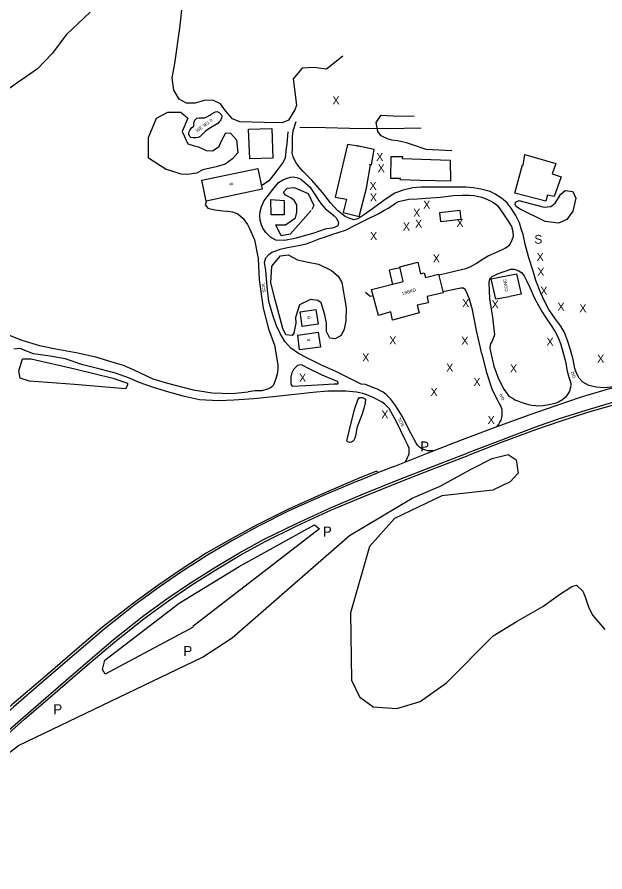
# Model space of a CAD drawing. Extents: x 2030130 to 2036320, y 723205 to 762423.
# Drawn here: x 2034000 to 2034735, y 739838 to 740906 of the extents above; entities that cross this region are included whole.
import ezdxf

# ---------------------------------------------------------------- set-up
doc = ezdxf.new("R2010")
doc.units = 0
for name, color, linetype in [('Draft_Station Labels Major', 7, 'Continuous'), ('Draft_Station Tics Major', 7, 'Continuous'), ('Draft_Station Tics Minor', 7, 'Continuous'), ('Exist Terrain Model Ground Surface', 7, 'Continuous'), ('Old_Level_23', 7, 'Continuous'), ('Old_Level_28', 7, 'Continuous'), ('Prop Alignment Horizontal', 7, 'Continuous'), ('Prop Alignment Vertical', 7, 'Continuous'), ('Prop Horizontal Alignment Ramp', 7, 'Continuous')]:
    doc.layers.add(name, color=color, linetype=linetype)

msp = doc.modelspace()

# ---------------------------------------------------------------- linework, layer by layer
at = {"layer": 'Draft_Station Labels Major'}
for p, q in [((2034469.7, 740344.2), (2034513.5, 740361.4)), ((2034518.8, 740344.3), (2034562.3, 740361.2)), ((2034520, 740341.6), (2034563.5, 740358.3)), ((2034425.9, 740326.7), (2034450.1, 740336.4)), ((2034449.1, 740338.7), (2034451.3, 740336.8))]:
    msp.add_line(p, q, dxfattribs=at)
for points in [[(2034591.3, 740688), (2034579.5, 740691), (2034570.1, 740692.6), (2034561, 740693.4), (2034549.3, 740693.5), (2034536.5, 740693.4), (2034517.6, 740693.4), (2034504.3, 740693.5), (2034494.4, 740692.8), (2034482.3, 740689.8), (2034472, 740686.1), (2034459.9, 740678), (2034443.8, 740666.6), (2034432.8, 740658.5), (2034427.7, 740655.2), (2034423.8, 740653.4), (2034420.5, 740652.9), (2034417.3, 740653.8), (2034413.5, 740655.1), (2034409.6, 740657), (2034400, 740664.6), (2034391.5, 740674.1), (2034381.4, 740686.8), (2034367.9, 740702.4), (2034356.9, 740713.5), (2034351.4, 740719.9), (2034348.6, 740723.9), (2034346, 740728.5), (2034344.7, 740731.5), (2034343.7, 740736.3), (2034343.9, 740740.4), (2034344, 740744.1), (2034344, 740748.5), (2034344.1, 740756.8), (2034344.9, 740763.9), (2034348.4, 740775.8)], [(2034338.2, 740762.7), (2034336.8, 740747.7), (2034335.9, 740742.5), (2034334.6, 740730.3), (2034332.1, 740724.9), (2034325.8, 740716.3), (2034319.5, 740707.7), (2034314.2, 740701.3), (2034305, 740695.3)], [(2034384.8, 740640.9), (2034370.8, 740636.1), (2034357.2, 740632.4), (2034347, 740629.6), (2034333.9, 740626.7), (2034323.2, 740627.5), (2034316.5, 740631.1), (2034310.6, 740637), (2034307, 740642.3), (2034305, 740646.6), (2034303.6, 740652.4), (2034303.1, 740658.1), (2034303.6, 740663.2), (2034305.1, 740668.9), (2034308.1, 740676.1), (2034319.2, 740690.8), (2034326.4, 740699.3), (2034331.8, 740702.9), (2034337.1, 740704.9), (2034341.6, 740706.2), (2034345.3, 740706.5), (2034350.5, 740705.4), (2034354.5, 740703.4), (2034356.6, 740702.1), (2034366, 740693.6), (2034369.5, 740688.2), (2034372.9, 740682.7), (2034376.5, 740677.2), (2034379.2, 740673.2), (2034384.9, 740666.8), (2034389.5, 740663), (2034392.7, 740660.5), (2034396.1, 740657.7), (2034399, 740654.7), (2034401.6, 740649.5), (2034400.5, 740645.3), (2034397.1, 740643.4), (2034393.5, 740642.5), (2034387, 740641.5), (2034384.9, 740641.1)], [(2034749.2, 740444.3), (2034734.1, 740442.7), (2034723.5, 740443.5), (2034714.6, 740445.5), (2034707.1, 740449.8), (2034702.5, 740454.7), (2034699.3, 740460.1), (2034697, 740466.8), (2034694.9, 740478.1), (2034691.7, 740490.3), (2034687.9, 740501.9), (2034684, 740511.9), (2034679.4, 740519.7), (2034672.1, 740530), (2034664.4, 740540.5), (2034659.3, 740550.2), (2034654.3, 740561.2), (2034648.3, 740576.7), (2034644.8, 740588.4), (2034639.5, 740605.4), (2034635, 740622.4), (2034632.3, 740634.2), (2034630, 740641.4), (2034627.6, 740648.8), (2034623.1, 740658.1), (2034617.4, 740667.4), (2034612.3, 740673.8), (2034605.2, 740679.9), (2034597.2, 740684.9), (2034591.3, 740688)], [(2034236.4, 740676.3), (2034234.8, 740671.5), (2034238, 740667.4), (2034246.6, 740665.4), (2034256.7, 740664), (2034262.8, 740663.7), (2034268.8, 740662.8), (2034275.7, 740660.1), (2034282.4, 740654.5), (2034287.8, 740646.9), (2034290, 740642), (2034296.6, 740627.6), (2034301, 740604.6), (2034302.4, 740577.7), (2034307.1, 740542.3), (2034314.1, 740516.6), (2034321.3, 740496.1), (2034325.6, 740471.3), (2034325.7, 740466), (2034324.6, 740459.9), (2034323.1, 740454.3), (2034321.6, 740449.5), (2034319.6, 740445.6), (2034318, 740443.8), (2034316.3, 740442.6), (2034314, 740441.5), (2034309.7, 740440.2), (2034305, 740439.2), (2034301, 740439.1), (2034297.2, 740438.9), (2034288.3, 740437.6)], [(2034422.4, 740451.1), (2034398, 740463), (2034379.2, 740471.7), (2034361.9, 740480.2), (2034351.6, 740485.5), (2034341.8, 740492.4), (2034334.2, 740500.5), (2034328.5, 740510.7), (2034324.1, 740520.4), (2034319.2, 740533.4), (2034314.4, 740550.7), (2034312.2, 740569), (2034310.6, 740589.4), (2034309.1, 740599.5), (2034310.7, 740605.3), (2034314.3, 740609.5), (2034318.1, 740612.2), (2034324.4, 740614.4), (2034328.6, 740615.9), (2034337.5, 740618), (2034351.3, 740620.5), (2034361.2, 740622.8), (2034367, 740624.8), (2034372.9, 740627.3), (2034377.4, 740629), (2034385.3, 740631.6), (2034393, 740634.2), (2034402.3, 740637.5), (2034410.2, 740640), (2034424, 740646.8), (2034435.6, 740652.6), (2034451.9, 740660.6), (2034458.3, 740664.3), (2034464.3, 740667.8), (2034469.6, 740671.5), (2034472.7, 740673.6), (2034476.5, 740675.6), (2034489.3, 740678.7), (2034500, 740679.1), (2034517, 740680.2), (2034528.9, 740681.1), (2034545.4, 740683), (2034556, 740683.4), (2034565.1, 740683.5), (2034571.1, 740683.1), (2034575, 740682.5), (2034580.6, 740681), (2034587.7, 740678.3), (2034593.9, 740675.2), (2034600.4, 740670.6)], [(2034600.4, 740670.6), (2034607.9, 740660), (2034613.7, 740650.9), (2034617.6, 740644.4), (2034619.4, 740638.3), (2034620, 740631.7), (2034618.3, 740627.2), (2034616.2, 740622.8), (2034613.6, 740619.9)], [(2034526.8, 740583.9), (2034534.4, 740585.6), (2034549.8, 740589.2), (2034560.8, 740591.7), (2034566.2, 740593.8), (2034573.5, 740598.1), (2034580.3, 740602.6), (2034588.6, 740607.7), (2034595.2, 740610.8), (2034601.9, 740613.4), (2034607.2, 740615.9), (2034610.3, 740617.7), (2034613.6, 740619.9)], [(2034617.7, 740590.9), (2034600, 740585), (2034593.1, 740581.6), (2034590.4, 740578.5), (2034589.5, 740574.2), (2034590.4, 740554.1), (2034594.2, 740531.2), (2034596.5, 740509.1), (2034593.6, 740501.1), (2034592, 740498.5), (2034590.9, 740496.1), (2034590.7, 740492.4), (2034591.4, 740488.1)], [(2034617.7, 740590.9), (2034621.1, 740591.1), (2034626.3, 740589.4), (2034630.4, 740586.8), (2034633.7, 740582.9), (2034636.7, 740577), (2034640.8, 740568), (2034646.1, 740555.7), (2034651.5, 740545.5), (2034656.5, 740536.8), (2034660.2, 740531.1), (2034666.6, 740521.8), (2034671.9, 740513.4), (2034675.5, 740506.5), (2034679, 740498), (2034681.7, 740489.5), (2034685.2, 740475.6), (2034687.4, 740463.7), (2034688.7, 740458.8), (2034690, 740455), (2034691.4, 740450.4), (2034691.8, 740447.4), (2034691.4, 740443.3), (2034690.3, 740438.7), (2034687.7, 740434.3), (2034684.9, 740430.7), (2034681.4, 740427.9), (2034676.4, 740424.7), (2034672, 740423.1), (2034664.8, 740421.3), (2034657.1, 740420.2), (2034650, 740419.8), (2034646.8, 740420.5)], [(2034580.7, 740485.3), (2034574, 740514.3), (2034569, 740540.3), (2034564.8, 740554.9), (2034560.2, 740565.4), (2034557.6, 740567.3), (2034554.6, 740567.4), (2034531.9, 740562.8)], [(2034513.5, 740361.4), (2034556.5, 740378.1), (2034598.8, 740394), (2034641, 740409.6), (2034672.2, 740420.4), (2034705.3, 740431.5), (2034739.1, 740441.7), (2034784.5, 740453.5), (2034831.3, 740463.8), (2034879.2, 740472.7), (2034926.3, 740481), (2034973, 740488.8), (2035020, 740496.5), (2035066.9, 740504.4), (2035113, 740512), (2035158.9, 740520.4), (2035205.9, 740529.4), (2035250.4, 740540.2)], [(2035255.1, 740522.5), (2035209.6, 740512), (2035162.8, 740502.2), (2035125, 740493.7), (2035070.5, 740484.2), (2035023.1, 740476.5), (2034976.7, 740468.7), (2034930.6, 740460.9), (2034882.8, 740452.7), (2034835.3, 740442.9), (2034789.3, 740432.5), (2034744.9, 740421.2), (2034711.7, 740411.5), (2034678.4, 740400.8), (2034647.7, 740390.2), (2034606.1, 740374.8), (2034563.5, 740358.3)], [(2033989.8, 740508.7), (2034005.3, 740502.2), (2034027.6, 740495.8), (2034048.1, 740491.3), (2034075.4, 740486.4), (2034097.5, 740481.3), (2034118.2, 740475.3), (2034132.2, 740471.2), (2034145.6, 740465.1), (2034169.3, 740454.1), (2034187.7, 740448.5), (2034219.7, 740440.2), (2034243.3, 740436.7), (2034268.3, 740435.7), (2034288.3, 740437.6)], [(2035124.6, 740496.2), (2035069.9, 740487.1), (2035022.8, 740479.3), (2034976.1, 740471.2), (2034929.9, 740463.6), (2034882.3, 740455.2), (2034834.7, 740446), (2034788.5, 740435.7), (2034744, 740424.4), (2034710.7, 740414.5), (2034677.5, 740403.8), (2034646.6, 740393), (2034605.2, 740377.4), (2034562.3, 740361.2)], [(2034251.8, 740426.4), (2034227.5, 740427.8), (2034208.8, 740431.9), (2034189.1, 740437.2), (2034170.2, 740443.1), (2034152.2, 740449.5), (2034140.1, 740454.7), (2034122.4, 740461.1), (2034103.3, 740466.1), (2034081.6, 740471.7), (2034059.5, 740478.9), (2034040.7, 740482.5), (2034020, 740485.4), (2034007.3, 740490.3), (2034003.9, 740492), (2033995.4, 740491.1)], [(2034580.7, 740485.3), (2034586.2, 740463.3), (2034593.4, 740440.2), (2034600.5, 740426.4), (2034602.8, 740422.5), (2034604, 740420.2), (2034604.9, 740418.1), (2034605.5, 740416), (2034605.8, 740412.2), (2034605.8, 740408.1), (2034605.3, 740405.7), (2034604.3, 740402.3), (2034603.3, 740400.1), (2034601.8, 740397.6), (2034599.2, 740394.1)], [(2034591.4, 740488.1), (2034595.7, 740470), (2034601.4, 740454.1), (2034608.3, 740440.9), (2034614.6, 740432.4), (2034619.9, 740429.4), (2034622, 740427.8), (2034625.6, 740426.3), (2034629.8, 740425), (2034632.5, 740424.1), (2034636, 740422.9), (2034639.1, 740422.1), (2034643.3, 740421.1), (2034646.8, 740420.5)], [(2034401, 740450.2), (2034381.2, 740458.6), (2034363.9, 740467.1), (2034357.7, 740470.4), (2034355.1, 740471.5), (2034350, 740470.6), (2034345.2, 740465.7), (2034343.1, 740461.4), (2034342, 740456.3), (2034341.7, 740452.1), (2034341.9, 740447.4), (2034343.3, 740444.9), (2034360.7, 740445.6), (2034382.2, 740447.1), (2034395.5, 740447.7), (2034397.4, 740447.8), (2034399.2, 740447.9), (2034400.7, 740447.9), (2034401.1, 740448), (2034400.7, 740450)], [(2034519.9, 740363.9), (2034512.9, 740364.2), (2034510.6, 740364.8), (2034508.1, 740365.7), (2034505.3, 740366.9), (2034502.9, 740368.5), (2034500.4, 740370.9), (2034498.2, 740374.3), (2034492, 740386.2), (2034481, 740407.3), (2034472.9, 740420.8), (2034466.5, 740428.8), (2034463.6, 740431.9), (2034460.5, 740434.8), (2034457.3, 740437.2), (2034454, 740439.2), (2034450.2, 740441), (2034446.4, 740442.5), (2034435, 740446.9), (2034429.8, 740447.5), (2034422.4, 740451.1)], [(2034485.4, 740350.4), (2034488.3, 740356.3), (2034488.9, 740358.3), (2034489.6, 740360.5), (2034489.9, 740363.6), (2034489.8, 740367.4), (2034488.2, 740371), (2034484.7, 740377.7), (2034473.4, 740401), (2034464.7, 740416.8), (2034459.5, 740422.2), (2034456, 740424.8), (2034445, 740430.6), (2034436.9, 740433.8), (2034431.8, 740435.6), (2034428.2, 740436.6), (2034423.9, 740437.2), (2034410.5, 740438.6), (2034388.3, 740438.4), (2034369.4, 740437), (2034350.7, 740434.8), (2034323.3, 740432), (2034295.5, 740428.9), (2034270.5, 740427.2), (2034251.8, 740426.4)], [(2033787.2, 739839.8), (2033823.7, 739871.9), (2033859.5, 739903), (2033897.7, 739936.1), (2033934, 739967.2), (2033970.3, 739998.9), (2034007, 740030.6), (2034045.1, 740063.7), (2034082.3, 740095.7), (2034119.8, 740127.7), (2034158.2, 740158.1), (2034186.9, 740179.2), (2034216.4, 740199), (2034246.6, 740218.2), (2034276.9, 740236.1), (2034308.5, 740253.4), (2034347.9, 740272.9), (2034391.5, 740292.9), (2034432.8, 740310.1), (2034476.2, 740327.7), (2034518.8, 740344.3)], [(2034469.7, 740344.2), (2034451.3, 740336.8)], [(2034449.1, 740338.7), (2034425.1, 740329), (2034383.4, 740311.2), (2034339.1, 740291.2), (2034299.7, 740271.5), (2034266.7, 740253.4), (2034236, 740236), (2034204.8, 740215.5), (2034175.6, 740195.5), (2034145.1, 740173.5), (2034106.5, 740143.7), (2034068.8, 740111.4), (2034031.6, 740079.5), (2033993.1, 740046.5), (2033956.6, 740014.4), (2033956.6, 740014.4), (2033920.1, 739982.7), (2033883.4, 739951.3), (2033845.4, 739918.4), (2033809.6, 739886.7), (2033772.9, 739855.1)], [(2033789.4, 739837.7), (2033825.8, 739869.5), (2033861.6, 739900.5), (2033899.9, 739933.6), (2033935.8, 739965), (2033972.5, 739996.4), (2034009, 740028.4), (2034047, 740061.6), (2034084.1, 740093.5), (2034121.6, 740125.3), (2034160.1, 740155.6), (2034188.7, 740176.6), (2034218.2, 740196.4), (2034248.2, 740215.4), (2034278.5, 740233.4), (2034309.9, 740250.5), (2034349.4, 740270.2), (2034392.6, 740290.2), (2034434.1, 740307.5), (2034477.2, 740325), (2034520, 740341.6)], [(2034425.9, 740326.7), (2034384.2, 740309), (2034340.1, 740289.4), (2034300.7, 740269.4), (2034267.9, 740251.4), (2034237.5, 740233.6), (2034206.3, 740213.4), (2034177.1, 740193.5), (2034146.9, 740171.4), (2034108.6, 740141.1), (2034070.9, 740109.2), (2034033.6, 740077.1), (2033995.4, 740044), (2033958.7, 740011.9)]]:
    msp.add_lwpolyline(points, dxfattribs=at)
at = {"layer": 'Draft_Station Tics Major'}
for points in [[(2034090.8, 740912.5), (2034061.4, 740884.5), (2034043.5, 740860.8), (2034024.9, 740841.3), (2033994, 740820), (2033959.4, 740793.9), (2033930.2, 740765.3), (2033913.6, 740749.1), (2033892.6, 740742.5), (2033864.1, 740744.9), (2033846.1, 740752.5), (2033832.3, 740760.2), (2033808.9, 740775.8), (2033785.9, 740810.4), (2033777.6, 740845.7), (2033776.5, 740887.4), (2033777, 740928.6)], [(2034406.8, 740857.1), (2034386.3, 740841.1), (2034370.7, 740843.2), (2034356, 740842.4), (2034344.9, 740829.1), (2034348.9, 740796.1), (2034346.9, 740790.3), (2034338.9, 740777.1), (2034330.8, 740774.1), (2034308.4, 740774.5), (2034278.2, 740775.2), (2034268.7, 740778.9), (2034260, 740788.9), (2034253.8, 740797.9), (2034244.2, 740802.3), (2034233.3, 740802), (2034222.1, 740798.6), (2034211.3, 740798.7), (2034202.4, 740803.6), (2034195.4, 740814.6), (2034193.3, 740830.2), (2034196.9, 740848), (2034203, 740892.3), (2034207, 740926.6)], [(2034174, 740779.6), (2034188.1, 740787.3), (2034204.5, 740787.4), (2034212.9, 740780), (2034205.8, 740763), (2034213.2, 740747.7), (2034219.9, 740745.6), (2034226.3, 740743.8), (2034235.9, 740739.4), (2034244, 740738.8), (2034252.1, 740744.4), (2034255.2, 740751.6), (2034260.7, 740761.6), (2034266.2, 740761.1), (2034273.7, 740752.8), (2034275.6, 740736.4), (2034268.7, 740729), (2034259.6, 740722.2), (2034248.6, 740718.8), (2034231.7, 740715.4), (2034223.8, 740710.9), (2034212.8, 740709.2), (2034204.9, 740709.8), (2034190.6, 740714.3), (2034186, 740715.6)], [(2034543.1, 740738.9), (2034511.1, 740740.8), (2034493.8, 740746.6), (2034486.5, 740749.1), (2034475.2, 740751.5), (2034468.3, 740752.5), (2034463.4, 740753.7), (2034454.9, 740757.7), (2034450.7, 740763.3), (2034448.5, 740774.4), (2034454.8, 740783.6), (2034470, 740782.6), (2034496, 740782.3)], [(2034186, 740715.6), (2034163.9, 740729.7), (2034163.9, 740755.8), (2034174, 740779.6)], [(2034367.1, 740664.6), (2034341.1, 740634.7), (2034329.7, 740632.9), (2034322.9, 740646.4), (2034335.3, 740646.6), (2034347.5, 740655.4), (2034349.5, 740662.2), (2034349.2, 740671.5), (2034346.6, 740676.3), (2034341.7, 740680.4), (2034335.3, 740683.5), (2034332.8, 740687.3), (2034337.3, 740692.4), (2034346.1, 740693.1), (2034363.7, 740685.8), (2034370.6, 740670.7), (2034367.9, 740665.5)], [(2034627.1, 740676.8), (2034658.7, 740668.7), (2034666.8, 740669.2), (2034672.4, 740673.4), (2034679.6, 740685), (2034684.8, 740689.3), (2034694.5, 740688.2), (2034698.4, 740679.8), (2034694.4, 740663.5), (2034686.9, 740653.2), (2034676.7, 740648.4), (2034659.7, 740650.5), (2034628.7, 740665.9), (2034623.9, 740668.9), (2034622.3, 740671.7), (2034622.7, 740674.7), (2034627.2, 740677)], [(2034322.1, 740552.6), (2034316.8, 740573.8), (2034317.9, 740594.7), (2034329, 740607.9), (2034338.4, 740608.9), (2034350.1, 740602.8), (2034363.4, 740599.7), (2034376.5, 740597.3), (2034392.8, 740589.3), (2034401.2, 740582.3), (2034405.6, 740574.6)], [(2034405.6, 740574.6), (2034411.1, 740542.9), (2034410.7, 740526.6), (2034408.6, 740516.1), (2034404.6, 740508.1), (2034397.4, 740504), (2034390.7, 740504.7), (2034386.4, 740513), (2034386.5, 740523.4), (2034384.5, 740533.9), (2034379.7, 740549), (2034375.4, 740552.1), (2034366.4, 740553.1), (2034352.7, 740546.6), (2034347.7, 740530.6), (2034347.9, 740523.4), (2034345.4, 740511.1), (2034343.4, 740508.1), (2034335.5, 740508.8), (2034331.8, 740516.8), (2034322.1, 740552.6)], [(2034135.2, 740441.7), (2034071.4, 740447.1), (2034015, 740450.9), (2034003.3, 740454.7), (2034001.6, 740463.8), (2034006.3, 740479.1)], [(2034006.3, 740479.1), (2034017.3, 740479.2), (2034071.9, 740466.3), (2034119.1, 740454.8), (2034137.5, 740448.4), (2034137.6, 740445.9), (2034135.2, 740441.7)], [(2034421.9, 740417.1), (2034425.7, 740427.7), (2034427.6, 740430.5), (2034431.6, 740430.5), (2034435.2, 740428.4), (2034434.9, 740424.2), (2034433, 740416.9), (2034430.5, 740408.9), (2034424.5, 740392.8), (2034423.2, 740384.5), (2034422, 740379.9), (2034420.3, 740376.6), (2034417.9, 740374.9), (2034415.1, 740374.6), (2034413.2, 740375.3), (2034411.9, 740376.3), (2034412.1, 740378)], [(2034412.1, 740378), (2034417.3, 740399.1), (2034421.9, 740417.1)], [(2033955.6, 739960.5), (2034001.2, 739995.5), (2034231.5, 740106.2), (2034268.3, 740130.3), (2034415.3, 740258.2), (2034493.5, 740304.9), (2034528.5, 740319.8), (2034567.4, 740341.1), (2034593.5, 740354.4), (2034613.7, 740359.6), (2034623.5, 740352.6), (2034626.1, 740336.1), (2034616.2, 740325.4), (2034594.6, 740314.9), (2034530.7, 740307.8), (2034471.5, 740279.6), (2034440.1, 740244.6), (2034416.4, 740161.6), (2034417.5, 740077.4), (2034427.5, 740056.5), (2034444.9, 740043.9), (2034474.5, 740042), (2034503.7, 740050.8), (2034536.5, 740074.1), (2034594.8, 740132.6), (2034624.9, 740151.2), (2034657, 740169.4), (2034677.8, 740184.4), (2034693.3, 740194.6), (2034699.2, 740196)], [(2034219.6, 740143.7), (2034109.8, 740084.7), (2034106.4, 740090.6), (2034109.2, 740102.3), (2034202.2, 740173.7), (2034277.4, 740219.5), (2034371.3, 740271.3), (2034377.5, 740266.7), (2034219.5, 740144.5)], [(2034699.2, 740196), (2034706.9, 740188.6), (2034709.7, 740181.4), (2034714.3, 740167.6), (2034719.6, 740158), (2034734.4, 740140.7)]]:
    msp.add_lwpolyline(points, dxfattribs=at)
at = {"layer": 'Draft_Station Tics Minor'}
msp.add_lwpolyline([(2034435.1, 740562.5), (2034441, 740557.2), (2034444.9, 740558)], dxfattribs=at)
at = {"layer": 'Exist Terrain Model Ground Surface'}
for points in [[(2034319.4, 740730), (2034290.5, 740728.9), (2034289, 740766), (2034317.9, 740767.1)], [(2034412.5, 740746.8), (2034397.4, 740681), (2034411.4, 740678.4), (2034407.1, 740662.1), (2034427.3, 740656.9), (2034436.5, 740692.2), (2034441.6, 740721.6), (2034440.2, 740721.9), (2034442.7, 740721.5), (2034446, 740740.8), (2034424.7, 740745.3), (2034426.6, 740744.9)], [(2034541.4, 740701.1), (2034503.4, 740702), (2034503.6, 740702.1), (2034478.7, 740702.9), (2034478.9, 740704.6), (2034478.9, 740704.6), (2034466.8, 740704.4), (2034467.4, 740731.8), (2034481.6, 740731.7), (2034481.1, 740729.2), (2034541.1, 740727.2)], [(2034622, 740686.2), (2034631.5, 740721.5), (2034632.2, 740720.9), (2034634.3, 740734.2), (2034673.1, 740723.1), (2034668.5, 740710.4), (2034680, 740706.6), (2034671.1, 740681.8), (2034662.9, 740683.5), (2034660.5, 740675.9)], [(2034305.9, 740690.9), (2034236.1, 740676.2), (2034230.5, 740702.4), (2034300.4, 740717.1)], [(2034333.5, 740658.8), (2034317.3, 740659), (2034316.8, 740678), (2034333.7, 740677.1)], [(2034553.6, 740664.6), (2034527.7, 740661.6), (2034528.9, 740650.8), (2034554.7, 740653.7)], [(2034532.2, 740561.5), (2034512.4, 740556.7), (2034513.7, 740549), (2034500, 740546), (2034502.4, 740536.3), (2034468.9, 740527.2), (2034466.9, 740537.9), (2034451.5, 740533.3), (2034442.9, 740565.5), (2034482.5, 740575.6), (2034478.1, 740594.1), (2034500.7, 740599.9), (2034504, 740585.2), (2034508.7, 740586.4), (2034510.2, 740580.7), (2034526.5, 740585)], [(2034375.9, 740522.5), (2034356, 740519.2), (2034353.4, 740537.7), (2034373, 740540.7)], [(2034379, 740493.7), (2034352.8, 740490.3), (2034350.4, 740508.7), (2034376.1, 740512.2)]]:
    msp.add_lwpolyline(points, close=True, dxfattribs=at)
for points in [[(2034504.8, 740767.4), (2034462.8, 740766.4), (2034415.5, 740767.1), (2034385, 740767.7), (2034352.9, 740768)], [(2034478.5, 740592.6), (2034465, 740589.7), (2034468.9, 740572.1)], [(2034615.1, 740556.6), (2034598, 740553.5), (2034592.4, 740579.1), (2034624, 740585.3), (2034629.7, 740559.9), (2034615.7, 740556.9)]]:
    msp.add_lwpolyline(points, dxfattribs=at)
at = {"layer": 'Prop Alignment Horizontal'}
msp.add_lwpolyline([(2034250.7, 740773.3), (2034239.3, 740766.6), (2034234.8, 740763.3), (2034231.4, 740759.9), (2034228.5, 740757.1), (2034225.9, 740755.8), (2034223.6, 740755.4), (2034219.6, 740755.2), (2034216.7, 740755.6), (2034215.1, 740757.2), (2034214.2, 740759.6), (2034214.5, 740762.1), (2034215.9, 740765.4), (2034217.9, 740768.1), (2034220, 740769.3), (2034220.8, 740771.1), (2034220.7, 740772.9), (2034220.9, 740774.9), (2034221.7, 740777.4), (2034224.2, 740780), (2034227.2, 740780.1), (2034233.7, 740780.1), (2034236.9, 740781.5), (2034240.5, 740783.7), (2034244.5, 740786.1), (2034247.5, 740787.6), (2034249.9, 740788), (2034252.8, 740786.6), (2034254.6, 740784.5), (2034255.5, 740782.9), (2034255, 740779.8), (2034254.2, 740777.7), (2034253.6, 740776.4), (2034252.4, 740775.2), (2034250.4, 740773.3)], dxfattribs=at)

# ---------------------------------------------------------------- texts
at = {"layer": 'Draft_Station Tics Major'}
for p in [(2034393.9, 740797), (2034448.6, 740726.4), (2034450.4, 740712.3), (2034440.2, 740690.2), (2034440.7, 740675.7), (2034507.3, 740666.6), (2034494.8, 740656.5), (2034548.8, 740643.8), (2034481.9, 740639.4), (2034497.2, 740642.9), (2034440.9, 740627.5), (2034649.2, 740601.4), (2034519.4, 740599.5), (2034650, 740582.8), (2034653.8, 740559), (2034556.1, 740543.6), (2034592.9, 740542), (2034675.2, 740539.1), (2034702.6, 740537.2), (2034464.9, 740497), (2034555, 740496.6), (2034661.5, 740495.4), (2034431.1, 740475.7), (2034724.8, 740474.2), (2034536.1, 740463), (2034615.9, 740462), (2034352.1, 740450.3), (2034570.2, 740445.1), (2034516.5, 740432.6), (2034455, 740404.6), (2034587.9, 740397.6)]:
    msp.add_text('X', height=10, dxfattribs=at).set_placement(p)
at = {"layer": 'Exist Terrain Model Ground Surface'}
msp.add_text('S', height=11, dxfattribs=at).set_placement((2034646.4, 740622.9))
at = {"layer": 'Old_Level_23'}
for s, rotation, p in [('SOIL', 100.3946, (2034310.7, 740562.4)), ('GR', 103.0015, (2034698, 740455.5)), ('GR', 111.0485, (2034609.2, 740428.1)), ('SOIL', 117.5722, (2034484.1, 740395.5))]:
    msp.add_text(s, height=4, rotation=rotation, dxfattribs=at).set_placement(p)
at = {"layer": 'Old_Level_28'}
for s, rotation, p in [('B', 96.3437, (2034269.4, 740695.9)), ('CONC', 100.5451, (2034613.8, 740563.4)), ('1SBKD', 17.5164, (2034481.4, 740558.2)), ('B', 96.6065, (2034366.5, 740529.1)), ('B', 96.808, (2034366.2, 740501.1))]:
    msp.add_text(s, height=4, rotation=rotation, dxfattribs=at).set_placement(p)
at = {"layer": 'Prop Alignment Vertical'}
msp.add_text('WE 361.0', height=4, rotation=36.0871, dxfattribs=at).set_placement((2034224.8, 740762))
at = {"layer": 'Prop Horizontal Alignment Ramp'}
for p in [(2034503.7, 740363.2), (2034381.9, 740256.9), (2034207.4, 740107.5), (2034044.9, 740034.7)]:
    msp.add_text('P', height=12.5, dxfattribs=at).set_placement(p)

doc.saveas('drawing.dxf')
